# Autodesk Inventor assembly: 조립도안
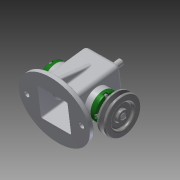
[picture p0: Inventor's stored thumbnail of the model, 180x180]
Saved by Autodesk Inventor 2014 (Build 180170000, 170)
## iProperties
Created: 2017-07
Part Number: 조립도안
Document SubType Name: Assembly
Designer: user
Author: user
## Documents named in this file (16)
- C:\Users\user\Desktop\470708V1007\조립도안.iam
- C:\Users\user\Desktop\470708V1007\V벨트풀리.ipt
- C:\Users\user\Desktop\470708V1007\고정핀 1.2 x  8.ipt
- C:\Users\user\Desktop\470708V1007\뒤커버.ipt
- C:\Users\user\Desktop\470708V1007\링크.ipt
- C:\Users\user\Desktop\470708V1007\멈춤나사 M3x8.ipt
- C:\Users\user\Desktop\470708V1007\베어링 12 x 32 x 10.ipt
- C:\Users\user\Desktop\470708V1007\본체.ipt
- C:\Users\user\Desktop\470708V1007\볼트 M4 x 12.ipt
- C:\Users\user\Desktop\470708V1007\부시.ipt
- C:\Users\user\Desktop\470708V1007\슬라이드.ipt
- C:\Users\user\Desktop\470708V1007\앞커버.ipt
- C:\Users\user\Desktop\470708V1007\오일실 12 25 7.ipt
- C:\Users\user\Desktop\470708V1007\키 4 x 4 x 10.ipt
- C:\Users\user\Desktop\470708V1007\편심축.ipt
- C:\Users\user\Desktop\470708V1007\핀 5 x 18.ipt
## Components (3 placed, 3 different names)
1. V벨트풀리:1 — Mate:10, Mate:12, Mate:13
2. 고정핀 1.2 x  8:1 — Mate:41, Mate:46, Flush:1, Mate:55
3. 핀 5 x 18:1 — Mate:41, Mate:43, Mate:44, Mate:46, Mate:55
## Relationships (9: Mate 8, Flush 1)
- Mate:10: V벨트풀리:1
- Mate:12: V벨트풀리:1
- Mate:13: V벨트풀리:1
- Mate:41: 고정핀 1.2 x  8:1 ↔ 핀 5 x 18:1
- Mate:43: 핀 5 x 18:1
- Mate:44: 핀 5 x 18:1
- Mate:46: 고정핀 1.2 x  8:1 ↔ 핀 5 x 18:1
- Flush:1: 고정핀 1.2 x  8:1
- Mate:55: 고정핀 1.2 x  8:1 ↔ 핀 5 x 18:1
